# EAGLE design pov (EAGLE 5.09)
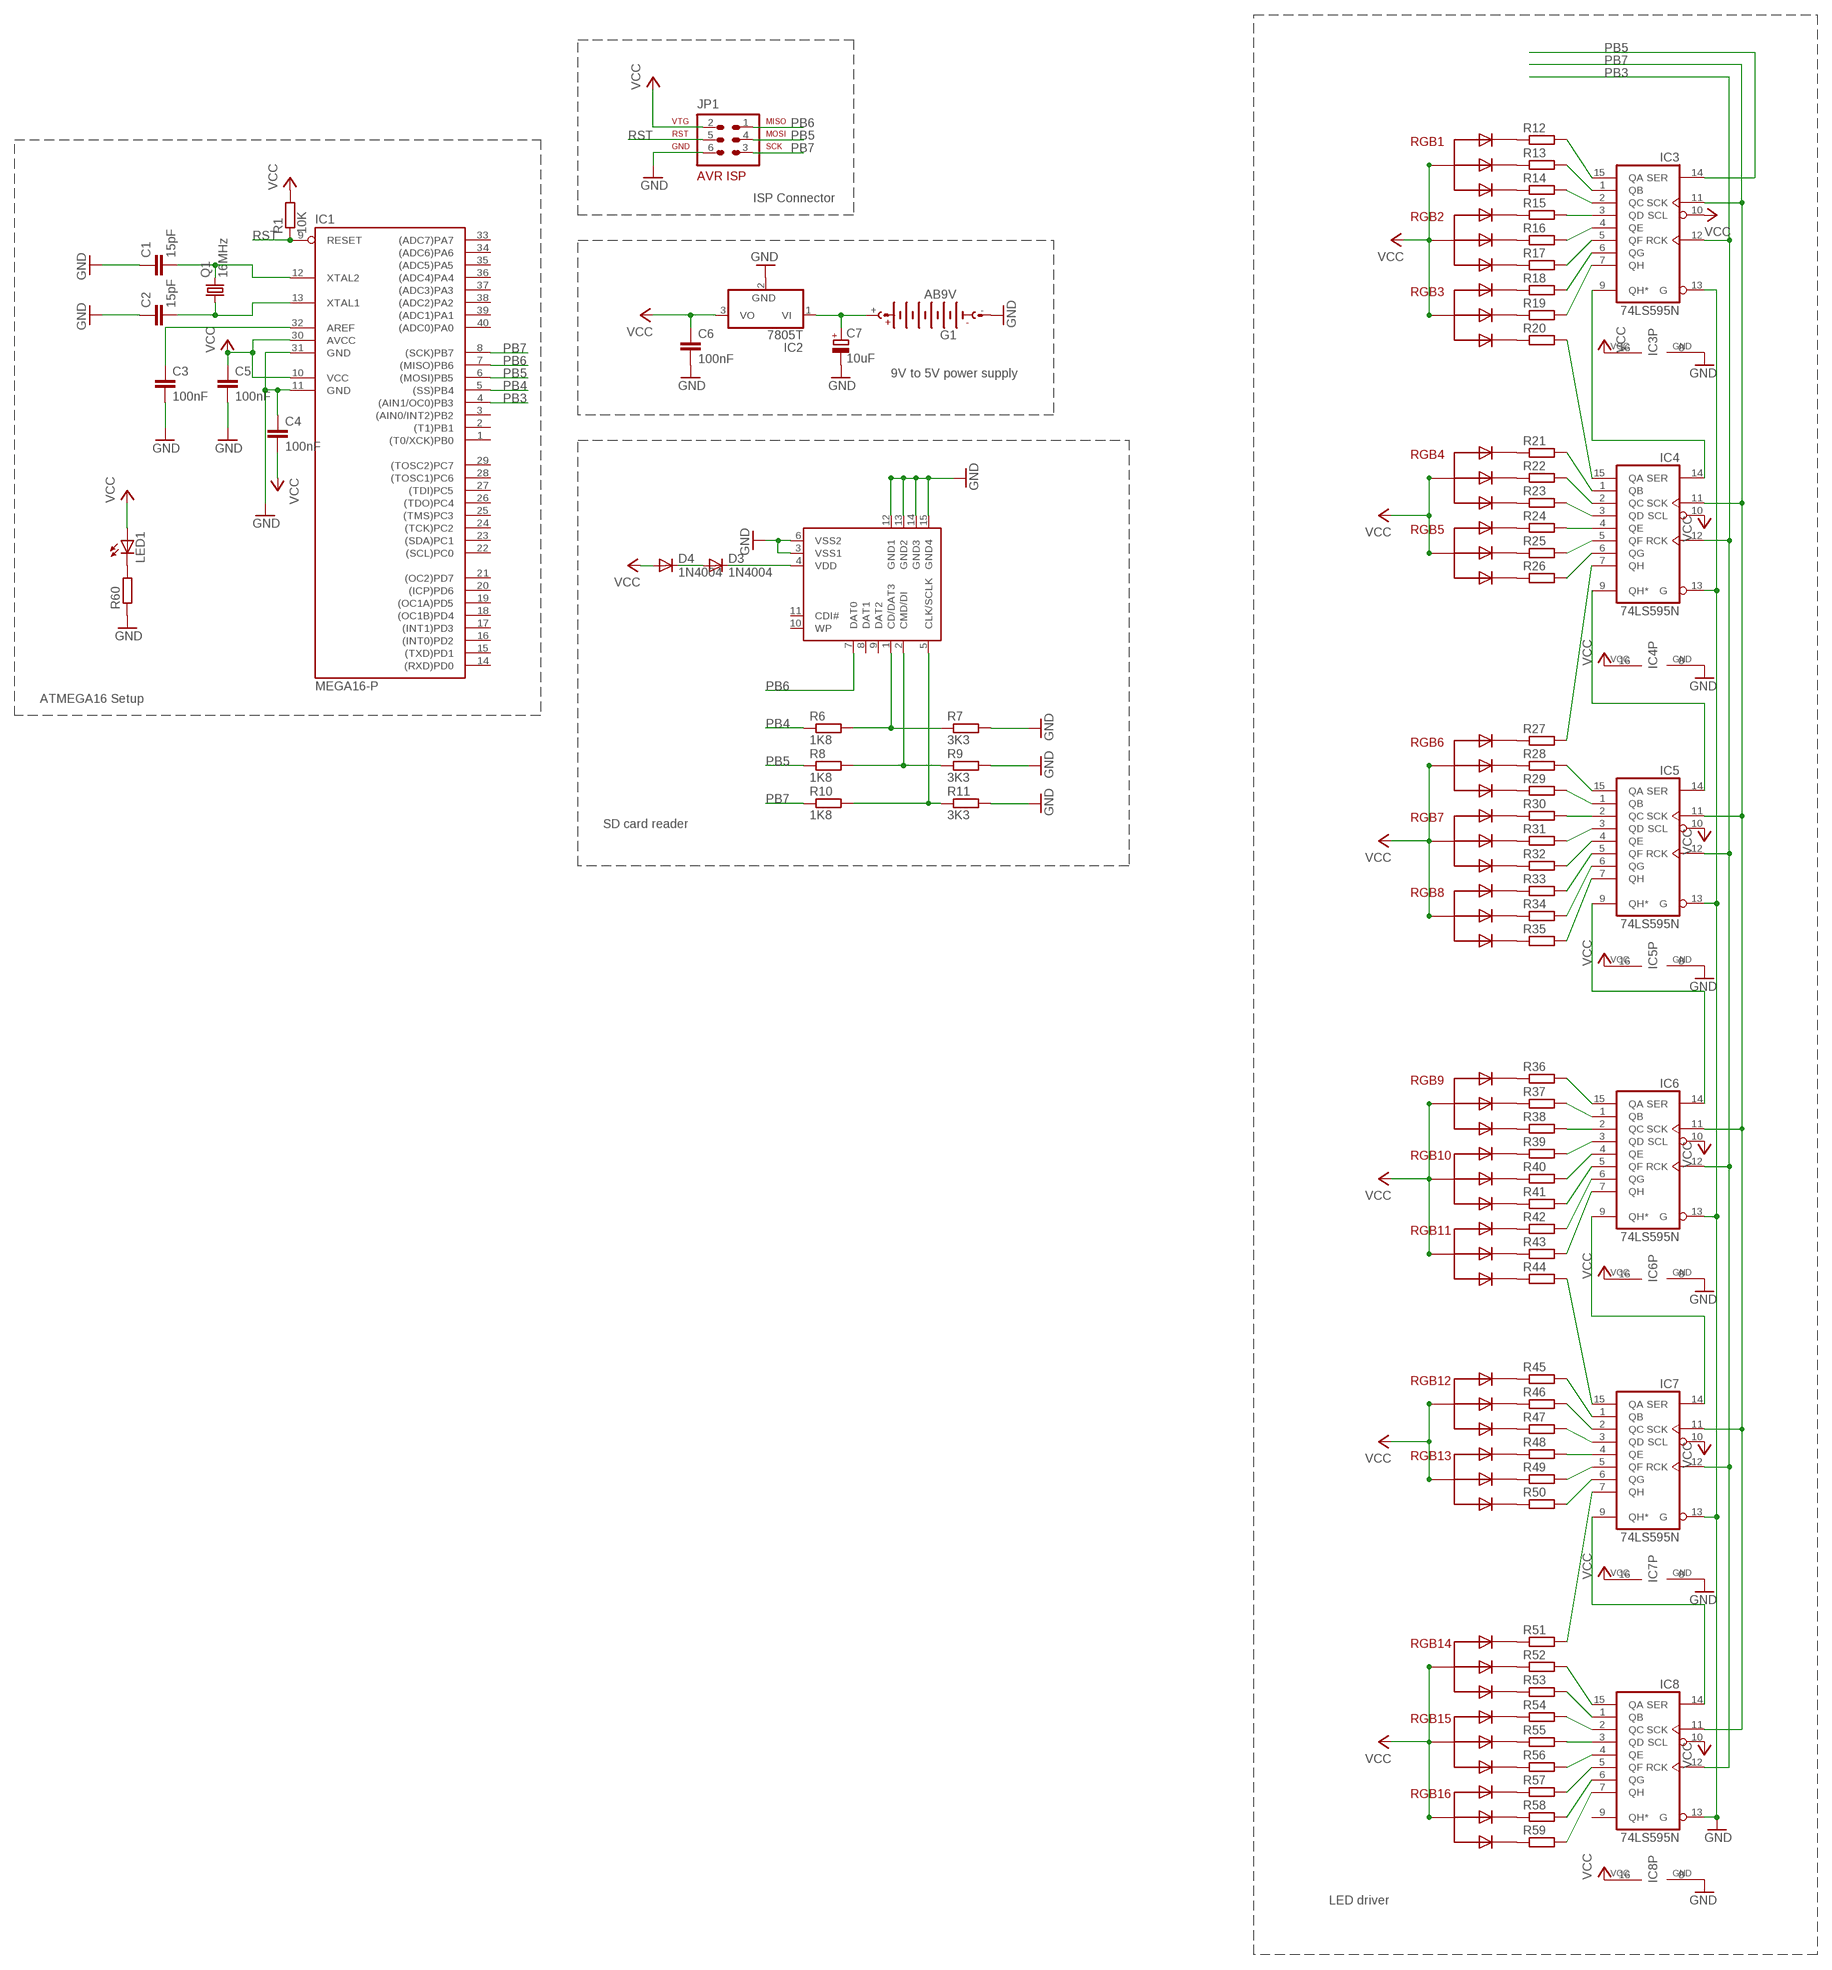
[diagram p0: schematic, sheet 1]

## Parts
C1  15pF  C-EU050-025X075  [C050-025X075]
C2  15pF  C-EU050-025X075  [C050-025X075]
C3  100nF  C-EU050-025X075  [C050-025X075]
C4  100nF  C-EU050-025X075  [C050-025X075]
C5  100nF  C-EU050-025X075  [C050-025X075]
C6  100nF  C-EU050-025X075  [C050-025X075]
C7  10uF  CPOL-EUE2,5-6E  [E2,5-6E]
D3  1N4004  [DO41-10]
D4  1N4004  [DO41-10]
G1  AB9V  [AB9V]
IC1  MEGA16-P  [DIL40]
IC2  7805T  [TO220H]
IC3  74LS595N  [DIL16]
IC4  74LS595N  [DIL16]
IC5  74LS595N  [DIL16]
IC6  74LS595N  [DIL16]
IC7  74LS595N  [DIL16]
IC8  74LS595N  [DIL16]
JP1  AVR-ISP-6  [AVR-ISP-6]
LED1  LED5MM  [LED5MM]
Q1  16MHz  CRYSTALHC49S  [HC49/S]
R1  10K  R-EU_0207/10  [0207/10]
R6  1K8  R-EU_0207/10  [0207/10]
R7  3K3  R-EU_0207/10  [0207/10]
R8  1K8  R-EU_0207/10  [0207/10]
R9  3K3  R-EU_0207/10  [0207/10]
R10  1K8  R-EU_0207/10  [0207/10]
R11  3K3  R-EU_0207/10  [0207/10]
R12  R-EU_M1206  [M1206]
R13  R-EU_M1206  [M1206]
R14  R-EU_M1206  [M1206]
R15  R-EU_M1206  [M1206]
R16  R-EU_M1206  [M1206]
R17  R-EU_M1206  [M1206]
R18  R-EU_M1206  [M1206]
R19  R-EU_M1206  [M1206]
R20  R-EU_M1206  [M1206]
R21  R-EU_M1206  [M1206]
R22  R-EU_M1206  [M1206]
R23  R-EU_M1206  [M1206]
R24  R-EU_M1206  [M1206]
R25  R-EU_M1206  [M1206]
R26  R-EU_M1206  [M1206]
R27  R-EU_M1206  [M1206]
R28  R-EU_M1206  [M1206]
R29  R-EU_M1206  [M1206]
R30  R-EU_M1206  [M1206]
R31  R-EU_M1206  [M1206]
R32  R-EU_M1206  [M1206]
R33  R-EU_M1206  [M1206]
R34  R-EU_M1206  [M1206]
R35  R-EU_M1206  [M1206]
R36  R-EU_M1206  [M1206]
R37  R-EU_M1206  [M1206]
R38  R-EU_M1206  [M1206]
R39  R-EU_M1206  [M1206]
R40  R-EU_M1206  [M1206]
R41  R-EU_M1206  [M1206]
R42  R-EU_M1206  [M1206]
R43  R-EU_M1206  [M1206]
R44  R-EU_M1206  [M1206]
R45  R-EU_M1206  [M1206]
R46  R-EU_M1206  [M1206]
R47  R-EU_M1206  [M1206]
R48  R-EU_M1206  [M1206]
R49  R-EU_M1206  [M1206]
R50  R-EU_M1206  [M1206]
R51  R-EU_M1206  [M1206]
R52  R-EU_M1206  [M1206]
R53  R-EU_M1206  [M1206]
R54  R-EU_M1206  [M1206]
R55  R-EU_M1206  [M1206]
R56  R-EU_M1206  [M1206]
R57  R-EU_M1206  [M1206]
R58  R-EU_M1206  [M1206]
R59  R-EU_M1206  [M1206]
R60  R-EU_0207/12  [0207/12]
RGB1  5MMRGBLEDAC  [LED5MMRGBAC]
RGB2  5MMRGBLEDAC  [LED5MMRGBAC]
RGB3  5MMRGBLEDAC  [LED5MMRGBAC]
RGB4  5MMRGBLEDAC  [LED5MMRGBAC]
RGB5  5MMRGBLEDAC  [LED5MMRGBAC]
RGB6  5MMRGBLEDAC  [LED5MMRGBAC]
RGB7  5MMRGBLEDAC  [LED5MMRGBAC]
RGB8  5MMRGBLEDAC  [LED5MMRGBAC]
RGB9  5MMRGBLEDAC  [LED5MMRGBAC]
RGB10  5MMRGBLEDAC  [LED5MMRGBAC]
RGB11  5MMRGBLEDAC  [LED5MMRGBAC]
RGB12  5MMRGBLEDAC  [LED5MMRGBAC]
RGB13  5MMRGBLEDAC  [LED5MMRGBAC]
RGB14  5MMRGBLEDAC  [LED5MMRGBAC]
RGB15  5MMRGBLEDAC  [LED5MMRGBAC]
RGB16  5MMRGBLEDAC  [LED5MMRGBAC]
U$1  SDCARDVAR2  [SDCMF-10915W010]

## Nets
GND: C1.1 C2.1 C3.2 C4.1 C5.2 C6.2 C7.- G1.- IC1.11(GND) IC1.31(GND) IC2.2(GND) IC3.8(GND) IC3.13(G) IC4.8(GND) IC4.13(G) IC5.8(GND) IC5.13(G) IC6.8(GND) IC6.13(G) IC7.8(GND) IC7.13(G) IC8.8(GND) IC8.13(G) JP1.6 R7.2 R9.2 R11.2 R60.1 U$1.3(VSS1) U$1.6(VSS2) U$1.12(GND1) U$1.13(GND2) U$1.14(GND3) U$1.15(GND4)
N$1: IC7.9(QH*) IC8.14(SER)
N$2: IC6.9(QH*) IC7.14(SER)
N$3: LED1.K(C) R60.2
N$4: R12.1 RGB1.RED
N$5: R13.1 RGB1.GRN(GREEN)
N$6: R14.1 RGB1.BLU(BLUE)
N$7: R15.1 RGB2.RED
N$8: R16.1 RGB2.GRN(GREEN)
N$9: R17.1 RGB2.BLU(BLUE)
N$10: R18.1 RGB3.RED
N$11: R19.1 RGB3.GRN(GREEN)
N$12: R20.1 RGB3.BLU(BLUE)
N$13: R21.1 RGB4.RED
N$14: R22.1 RGB4.GRN(GREEN)
N$15: R23.1 RGB4.BLU(BLUE)
N$16: R24.1 RGB5.RED
N$23: R25.1 RGB5.GRN(GREEN)
N$24: R6.2 R7.1 U$1.1(CD/DAT3)
N$25: R8.2 R9.1 U$1.2(CMD/DI)
N$26: D3.C U$1.4(VDD)
N$27: D3.A D4.C
N$28: R10.2 R11.1 U$1.5(CLK/SCLK)
N$29: R26.1 RGB5.BLU(BLUE)
N$30: R51.1 RGB14.RED
N$31: R27.1 RGB6.RED
N$32: R28.1 RGB6.GRN(GREEN)
N$33: R29.1 RGB6.BLU(BLUE)
N$34: R30.1 RGB7.RED
N$35: R31.1 RGB7.GRN(GREEN)
N$36: R32.1 RGB7.BLU(BLUE)
N$37: R33.1 RGB8.RED
N$38: R34.1 RGB8.GRN(GREEN)
N$39: R35.1 RGB8.BLU(BLUE)
N$40: IC3.15(QA) R12.2
N$41: IC3.1(QB) R13.2
N$42: IC3.2(QC) R14.2
N$43: IC3.3(QD) R15.2
N$44: IC3.4(QE) R16.2
N$45: IC3.5(QF) R17.2
N$46: IC3.6(QG) R18.2
N$47: IC3.7(QH) R19.2
N$48: IC4.15(QA) R20.2
N$49: IC4.1(QB) R21.2
N$50: IC4.2(QC) R22.2
N$51: IC4.3(QD) R23.2
N$52: IC4.4(QE) R24.2
N$53: IC4.5(QF) R25.2
N$54: IC4.6(QG) R26.2
N$55: IC4.7(QH) R27.2
N$56: IC5.15(QA) R28.2
N$57: IC5.1(QB) R29.2
N$58: IC5.2(QC) R30.2
N$59: IC5.3(QD) R31.2
N$60: IC5.4(QE) R32.2
N$61: IC5.5(QF) R33.2
N$62: IC5.6(QG) R34.2
N$63: IC5.7(QH) R35.2
N$64: IC6.15(QA) R36.2
N$65: IC6.1(QB) R37.2
N$66: IC6.2(QC) R38.2
N$67: R36.1 RGB9.RED
N$68: R37.1 RGB9.GRN(GREEN)
N$69: R38.1 RGB9.BLU(BLUE)
N$70: R39.1 RGB10.RED
N$71: R40.1 RGB10.GRN(GREEN)
N$72: R41.1 RGB10.BLU(BLUE)
N$73: IC3.9(QH*) IC4.14(SER)
N$74: R42.1 RGB11.RED
N$75: R43.1 RGB11.GRN(GREEN)
N$76: R44.1 RGB11.BLU(BLUE)
N$77: IC6.3(QD) R39.2
N$78: IC6.4(QE) R40.2
N$79: IC6.5(QF) R41.2
N$80: IC6.6(QG) R42.2
N$81: IC6.7(QH) R43.2
N$83: IC7.15(QA) R44.2
N$84: R45.1 RGB12.RED
N$85: R46.1 RGB12.GRN(GREEN)
N$86: R47.1 RGB12.BLU(BLUE)
N$87: R48.1 RGB13.RED
N$88: R49.1 RGB13.GRN(GREEN)
N$89: R50.1 RGB13.BLU(BLUE)
N$91: IC7.1(QB) R45.2
N$92: IC7.2(QC) R46.2
N$93: IC7.3(QD) R47.2
N$94: IC7.4(QE) R48.2
N$95: IC7.5(QF) R49.2
N$96: IC7.6(QG) R50.2
N$97: R52.1 RGB14.GRN(GREEN)
N$98: R53.1 RGB14.BLU(BLUE)
N$99: R54.1 RGB15.RED
N$100: R55.1 RGB15.GRN(GREEN)
N$101: R56.1 RGB15.BLU(BLUE)
N$102: R57.1 RGB16.RED
N$103: IC5.9(QH*) IC6.14(SER)
N$104: R58.1 RGB16.GRN(GREEN)
N$105: R59.1 RGB16.BLU(BLUE)
N$106: IC7.7(QH) R51.2
N$107: IC8.15(QA) R52.2
N$108: IC8.1(QB) R53.2
N$109: IC8.2(QC) R54.2
N$110: IC8.3(QD) R55.2
N$111: IC8.4(QE) R56.2
N$112: IC8.5(QF) R57.2
N$113: IC8.6(QG) R58.2
N$114: IC4.9(QH*) IC5.14(SER)
N$115: IC8.7(QH) R59.2
N$120: C1.2 IC1.12(XTAL2) Q1.2
N$121: C2.2 IC1.13(XTAL1) Q1.1
N$122: C3.1 IC1.32(AREF)
PB3: IC1.4((AIN1/OC0)PB3) IC3.12(RCK) IC4.12(RCK) IC5.12(RCK) IC6.12(RCK) IC7.12(RCK) IC8.12(RCK)
PB4: IC1.5((SS)PB4) R6.1
PB5: IC1.6((MOSI)PB5) IC3.14(SER) JP1.4 R8.1
PB6: IC1.7((MISO)PB6) JP1.1 U$1.7(DAT0)
PB7: IC1.8((SCK)PB7) IC3.11(SCK) IC4.11(SCK) IC5.11(SCK) IC6.11(SCK) IC7.11(SCK) IC8.11(SCK) JP1.3 R10.1
RST: IC1.9(RESET) JP1.5 R1.1
VCC: C4.2 C5.1 C6.1 D4.A IC1.10(VCC) IC1.30(AVCC) IC2.3(VO) IC3.10(SCL) IC3.16(VCC) IC4.10(SCL) IC4.16(VCC) IC5.10(SCL) IC5.16(VCC) IC6.10(SCL) IC6.16(VCC) IC7.10(SCL) IC7.16(VCC) IC8.10(SCL) IC8.16(VCC) JP1.2 LED1.A R1.2 RGB1.VCC RGB2.VCC RGB3.VCC RGB4.VCC RGB5.VCC RGB6.VCC RGB7.VCC RGB8.VCC RGB9.VCC RGB10.VCC RGB11.VCC RGB12.VCC RGB13.VCC RGB14.VCC RGB15.VCC RGB16.VCC
VCC9V: C7.+ G1.+ IC2.1(VI)
Unconnected: IC1.1((T0/XCK)PB0) IC1.2((T1)PB1) IC1.3((AIN0/INT2)PB2) IC1.14((RXD)PD0) IC1.15((TXD)PD1) IC1.16((INT0)PD2) IC1.17((INT1)PD3) IC1.18((OC1B)PD4) IC1.19((OC1A)PD5) IC1.20((ICP)PD6) IC1.21((OC2)PD7) IC1.22((SCL)PC0) IC1.23((SDA)PC1) IC1.24((TCK)PC2) IC1.25((TMS)PC3) IC1.26((TDO)PC4) IC1.27((TDI)PC5) IC1.28((TOSC1)PC6) IC1.29((TOSC2)PC7) IC1.33((ADC7)PA7) IC1.34((ADC6)PA6) IC1.35((ADC5)PA5) IC1.36((ADC4)PA4) IC1.37((ADC3)PA3) IC1.38((ADC2)PA2) IC1.39((ADC1)PA1) IC1.40((ADC0)PA0) IC8.9(QH*) U$1.8(DAT1) U$1.9(DAT2) U$1.10(WP) U$1.11(CDI#)

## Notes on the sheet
- ISP Connector
- 9V to 5V power supply
- ATMEGA16 Setup
- SD card reader
- LED driver

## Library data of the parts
C1-C6 = rcl:C-EU: CAPACITOR, European symbol
C7 = rcl:CPOL-EU: POLARIZED CAPACITOR, European symbol
D3 D4 = diode:1N4004: DIODE
G1 = battery:AB9V: 9-V BATTERY CLIP
IC1 = atmel:MEGA16-P: MICROCONTROLLER 16 Kbytes FLASH 1 kbytes SRAM 512 bytes EEPROM USART 8-channel 10 bit ADC Source: avr.lbr
IC2 = linear:78*: Positive VOLTAGE REGULATOR Source: http://cache.national.com/ds/LM/LM78L05.pdf http://www.fairchildsemi.com/ds/LM/LM7805.pdf
IC3-IC8 = 74xx-us:74*595: 8-bit SHIFT REGISTER, output latch
JP1 = avr-5:AVR-ISP-6: AVR ISP-6 Serial Programming Header
LED1 = led:LED: LED
Q1 = crystal:CRYSTAL: CRYSTAL
R1 R12-R60 = rcl:R-EU_: RESISTOR, European symbol
R6-R11 = resistor:R-EU_: RESISTOR, European symbol
RGB1-RGB16 = led_rgb2:5MMRGBLEDAC
U$1 = kingfont_sdcmf10915w010_covek:SDCARD: SD card connector KINGFONT SDCMF-10915W010

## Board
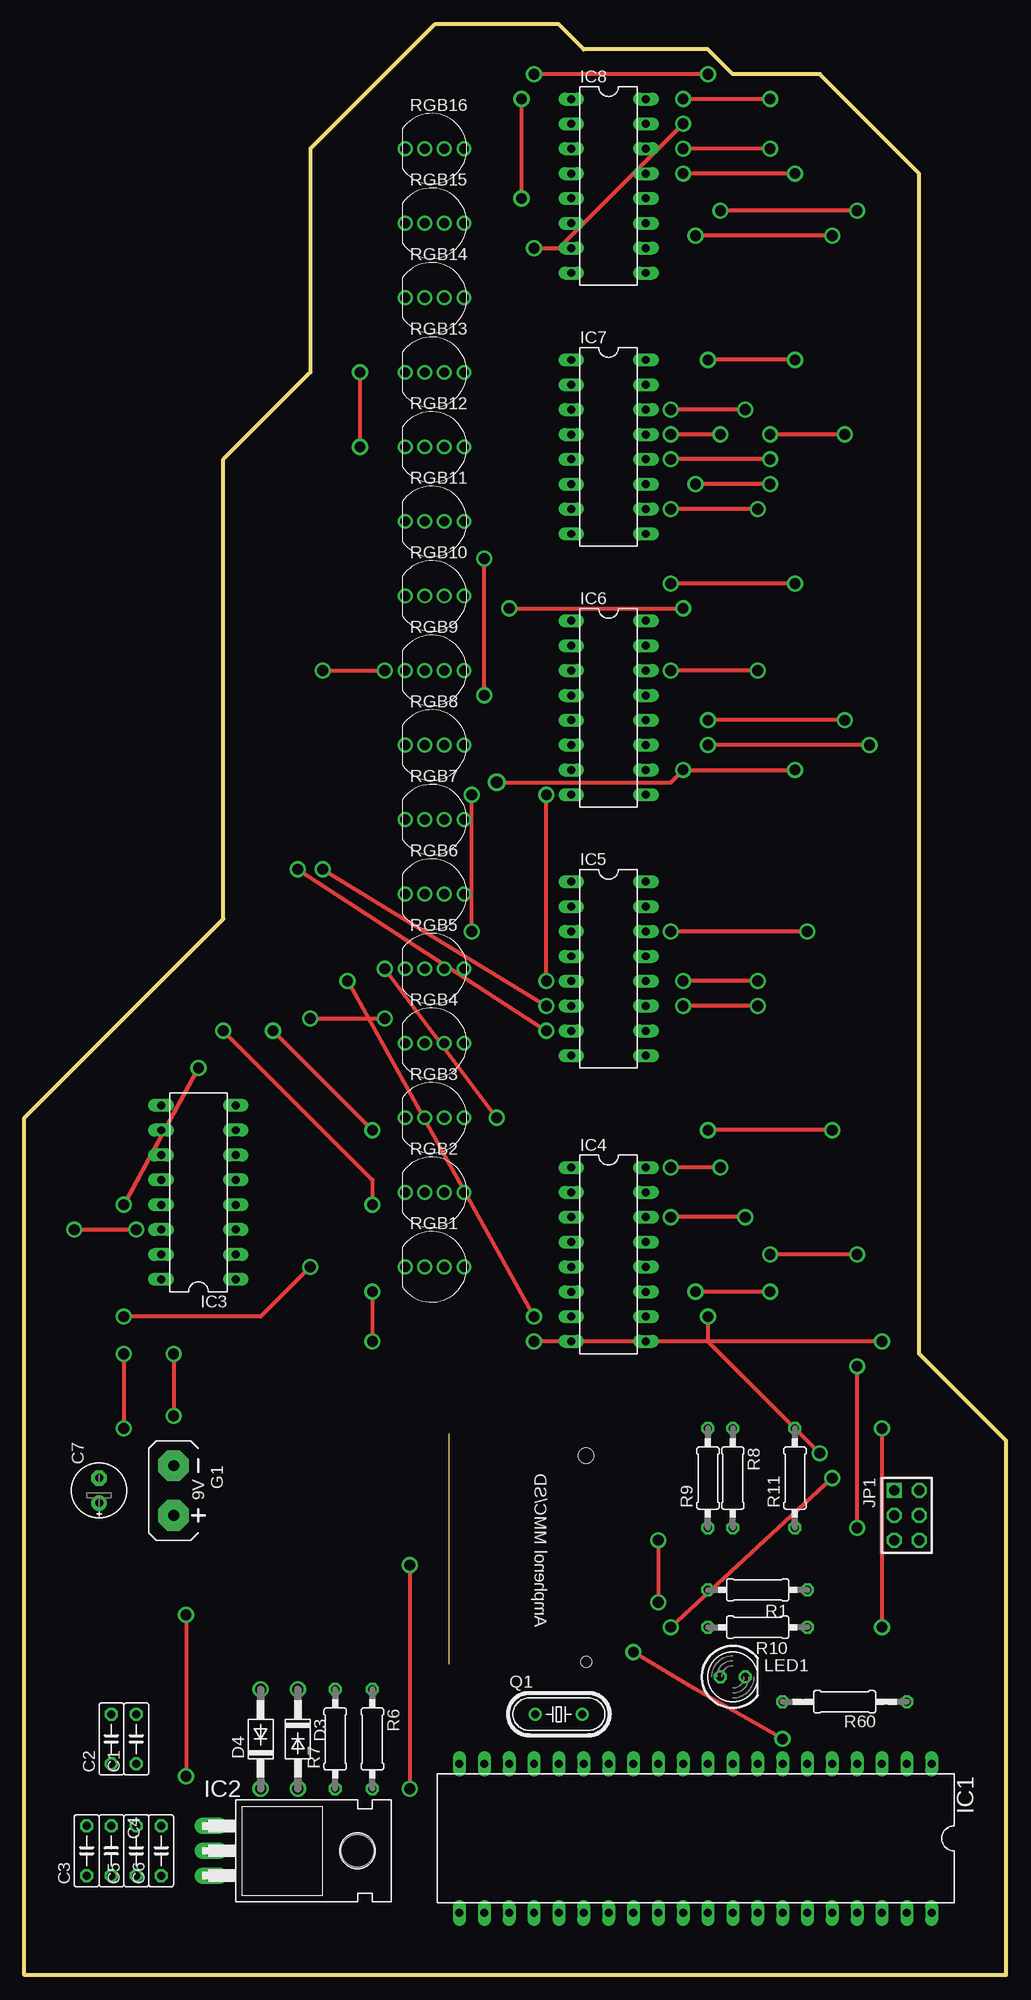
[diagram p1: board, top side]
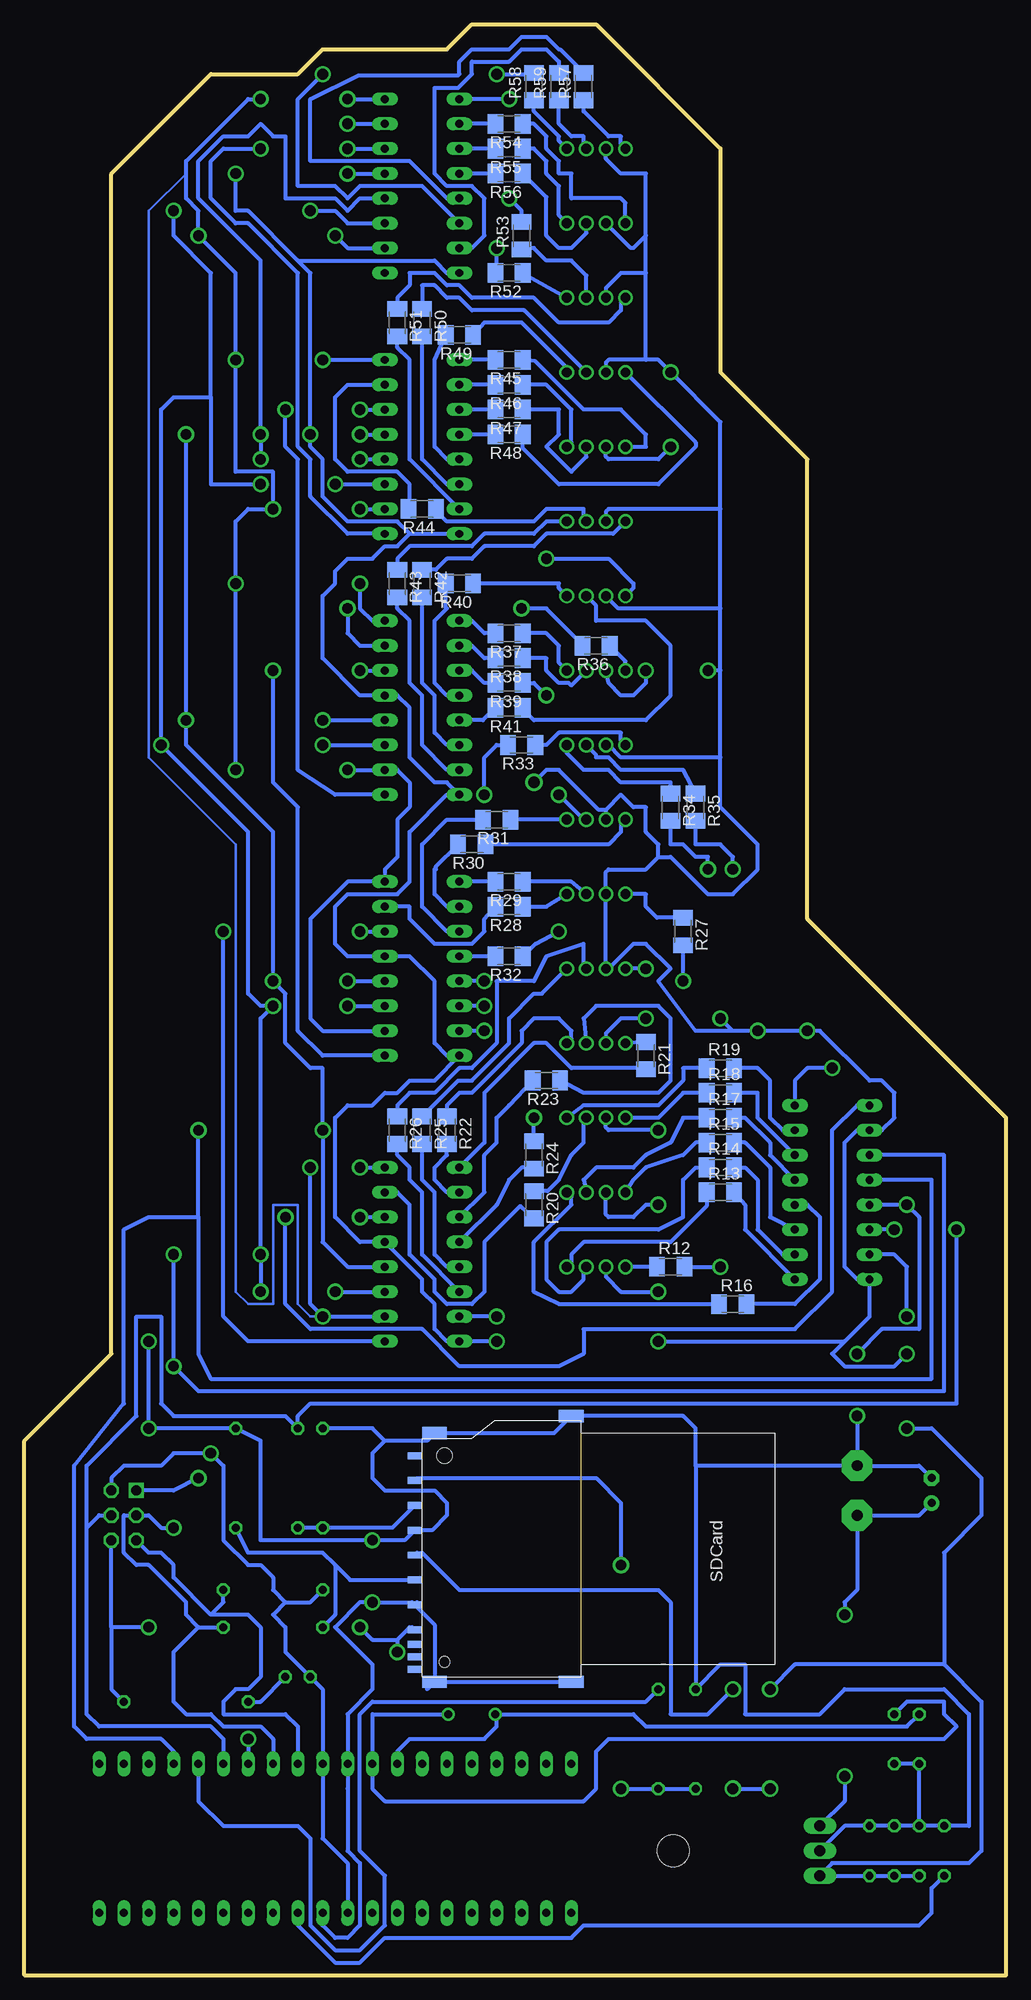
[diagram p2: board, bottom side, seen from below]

Size 100.33 x 199.39 mm. Coordinates in mm from the lower left corner, seen from the top.
Outline: 100.33,0 100.33,54.61 91.44,63.5 91.44,184.15 81.28,194.31 72.39,194.31 69.85,196.85 57.15,196.85 54.61,199.39 41.91,199.39 29.21,186.69 29.21,163.83 20.32,154.94 20.32,107.95 0,87.63 0,0 100.33,0
Copper layers (1*16): Top 0.035mm / dielectric 1.5mm / Bottom 0.035mm
Design rules "default": minimum track width 10mil, minimum drill 24mil, track to track 8mil, track to pad 8mil, pad to pad 8mil, via to via 8mil, smd to smd 8mil, copper to edge 40mil, drill to drill 8mil, minimum pad ring 10mil, minimum via ring 8mil, stop-mask expansion 4mil, vias tented up to drill 0mil, thermal gap 10mil

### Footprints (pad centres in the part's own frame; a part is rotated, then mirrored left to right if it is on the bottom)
C050-025X075 = drill 0.813 octagon: 1 -2.54,0; 2 2.54,0
E2,5-6E = drill 0.813 pad 1.575 round: + -1.27,0 | drill 0.813 pad 1.575 octagon: - 1.27,0
DO41-10 = drill 1.118 round: A 5.08,0; C -5.08,0
AB9V = drill 1.118 pad 3.15 octagon: + 0,2.54; - 0,-2.54
DIL40 = drill 0.813 long: 1 -24.13,-7.62; 2 -21.59,-7.62; 3 -19.05,-7.62; 4 -16.51,-7.62; 5 -13.97,-7.62; 6 -11.43,-7.62; 7 -8.89,-7.62; 8 -6.35,-7.62; 9 -3.81,-7.62; 10 -1.27,-7.62; 11 1.27,-7.62; 12 3.81,-7.62; 13 6.35,-7.62; 14 8.89,-7.62; 15 11.43,-7.62; 16 13.97,-7.62; 17 16.51,-7.62; 18 19.05,-7.62; 19 21.59,-7.62; 20 24.13,-7.62; 21 24.13,7.62; 22 21.59,7.62; 23 19.05,7.62; 24 16.51,7.62; 25 13.97,7.62; 26 11.43,7.62; 27 8.89,7.62; 28 6.35,7.62; 29 3.81,7.62; 30 1.27,7.62; 31 -1.27,7.62; 32 -3.81,7.62; 33 -6.35,7.62; 34 -8.89,7.62; 35 -11.43,7.62; 36 -13.97,7.62; 37 -16.51,7.62; 38 -19.05,7.62; 39 -21.59,7.62; 40 -24.13,7.62
TO220H = drill 1.118 long: 1 -2.54,-10.16; 2 0,-10.16; 3 2.54,-10.16 | hole 3.302: 0,4.826
DIL16 = drill 0.813 long: 1 -8.89,-3.81; 2 -6.35,-3.81; 3 -3.81,-3.81; 4 -1.27,-3.81; 5 1.27,-3.81; 6 3.81,-3.81; 7 6.35,-3.81; 8 8.89,-3.81; 9 8.89,3.81; 10 6.35,3.81; 11 3.81,3.81; 12 1.27,3.81; 13 -1.27,3.81; 14 -3.81,3.81; 15 -6.35,3.81; 16 -8.89,3.81
AVR-ISP-6 = drill 1.016 square: 1 -2.54,-1.27 | drill 1.016 octagon: 2 -2.54,1.27; 3 0,-1.27; 4 0,1.27; 5 2.54,-1.27; 6 2.54,1.27
LED5MM = drill 0.813 octagon: A -1.27,0; K 1.27,0
HC49/S = drill 0.813 round: 1 -2.413,0; 2 2.413,0
0207/10 = drill 0.813 octagon: 1 -5.08,0; 2 5.08,0
M1206 = smd 1.6 x 2: 1 -1.4,0; 2 1.4,0
0207/12 = drill 0.813 octagon: 1 -6.35,0; 2 6.35,0
LED5MMRGBAC = drill 1 round: BLU 1,0; GRN 3,0; RED -3,0; VCC -1,0
SDCMF-10915W010 = smd 0.711 x 1.422: 1 7.366,13.462; 2 4.826,13.462; 3 2.286,13.462; 4 -0.254,13.462; 5 -2.794,13.462; 6 -5.334,13.462; 7 -7.874,13.462; 8 -9.398,13.462; 9 9.906,13.462; 10 -11.938,13.462; 11 -10.668,13.462 | smd 1.27 x 2.54: 12 12.192,11.43; 13 13.97,-2.54; 14 -13.208,-2.54; 15 -13.208,11.43 | hole 1.6: 9.906,10.414 | hole 1.1: -11.176,10.414

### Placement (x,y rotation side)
C1  11.43,24.13 90 top
C2  8.89,24.13 90 top
C3  6.35,12.7 90 top
C4  8.89,12.7 270 top
C5  11.43,12.7 90 top
C6  13.97,12.7 90 top
C7  7.62,49.53 90 top
D3  27.94,24.13 270 top
D4  24.13,24.13 90 top
G1  15.24,49.53 180 top
IC1  68.58,13.97 180 top
IC2  29.21,12.7 270 top
IC3  17.78,80.01 90 top
IC4  59.69,73.66 270 top
IC5  59.69,102.87 270 top
IC6  59.69,129.54 270 top
IC7  59.69,156.21 270 top
IC8  59.69,182.88 270 top
JP1  90.17,46.99 270 top
LED1  72.39,30.48 0 top
Q1  54.61,26.67 0 top
R1  74.93,39.37 180 top
R6  35.56,24.13 270 top
R7  31.75,24.13 90 top
R8  72.39,50.8 270 top
R9  69.85,50.8 90 top
R10  74.93,35.56 180 top
R11  78.74,50.8 90 top
R12  34.29,72.39 0 bottom
R13  29.21,80.01 0 bottom
R14  29.21,82.55 0 bottom
R15  29.21,85.09 0 bottom
R16  27.94,68.58 0 bottom
R17  29.21,87.63 0 bottom
R18  29.21,90.17 0 bottom
R19  29.21,92.71 0 bottom
R20  48.26,78.74 270 bottom
R21  36.83,93.98 270 bottom
R22  57.15,86.36 270 bottom
R23  46.99,91.44 180 bottom
R24  48.26,83.82 270 bottom
R25  59.69,86.36 270 bottom
R26  62.23,86.36 270 bottom
R27  33.02,106.68 270 bottom
R28  50.8,109.22 180 bottom
R29  50.8,111.76 180 bottom
R30  54.61,115.57 180 bottom
R31  52.07,118.11 180 bottom
R32  50.8,104.14 180 bottom
R33  49.53,125.73 180 bottom
R34  34.29,119.38 270 bottom
R35  31.75,119.38 270 bottom
R36  41.91,135.89 180 bottom
R37  50.8,137.16 180 bottom
R38  50.8,134.62 180 bottom
R39  50.8,132.08 180 bottom
R40  55.88,142.24 180 bottom
R41  50.8,129.54 180 bottom
R42  59.69,142.24 270 bottom
R43  62.23,142.24 270 bottom
R44  59.69,149.86 180 bottom
R45  50.8,165.1 180 bottom
R46  50.8,162.56 180 bottom
R47  50.8,160.02 180 bottom
R48  50.8,157.48 180 bottom
R49  55.88,167.64 180 bottom
R50  59.69,168.91 270 bottom
R51  62.23,168.91 270 bottom
R52  50.8,173.99 180 bottom
R53  49.53,177.8 90 bottom
R54  50.8,189.23 180 bottom
R55  50.8,186.69 180 bottom
R56  50.8,184.15 180 bottom
R57  43.18,193.04 90 bottom
R58  48.26,193.04 90 bottom
R59  45.72,193.04 90 bottom
R60  83.82,27.94 180 top
RGB1  41.91,72.39 0 top
RGB2  41.91,80.01 0 top
RGB3  41.91,87.63 0 top
RGB4  41.91,95.25 0 top
RGB5  41.91,102.87 0 top
RGB6  41.91,110.49 0 top
RGB7  41.91,118.11 0 top
RGB8  41.91,125.73 0 top
RGB9  41.91,133.35 0 top
RGB10  41.91,140.97 0 top
RGB11  41.91,148.59 0 top
RGB12  41.91,156.21 0 top
RGB13  41.91,163.83 0 top
RGB14  41.91,171.45 0 top
RGB15  41.91,179.07 0 top
RGB16  41.91,186.69 0 top
U$1  46.99,43.18 90 bottom

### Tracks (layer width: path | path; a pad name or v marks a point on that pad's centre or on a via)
GND  (via drill 1.1)
  Top 0.406: v78.74,184.15 v67.31,184.15 | v71.12,157.48 v66.04,157.48 | v17.78,92.71 v10.16,78.74 | v15.24,63.5 v15.24,57.15 | v64.77,44.45 v64.77,38.1 | v87.63,55.88 v87.63,35.56 | v87.63,64.77 v52.07,64.77
  Bottom 0.406: v67.31,184.15 IC8.13 | IC8.8 57.15,173.99 58.42,175.26 72.39,175.26 | 60.96,147.32 IC7.8 | 60.96,147.32 62.23,148.59 67.31,148.59 69.85,151.13 69.85,154.94 71.12,156.21 v71.12,157.48 71.12,173.99 72.39,175.26 | 72.39,175.26 77.47,180.34 78.74,180.34 v78.74,184.15 | v66.04,157.48 IC7.13 | 60.96,147.32 62.23,146.05 63.5,146.05 64.77,144.78 67.31,144.78 68.58,143.51 68.58,142.24 69.85,140.97 69.85,134.62 66.04,130.81 IC6.13 62.23,130.81 60.96,129.54 60.96,124.46 58.42,121.92 57.15,121.92 IC6.8 57.15,120.65 60.96,116.84 60.96,111.76 62.23,110.49 67.31,110.49 68.58,109.22 68.58,105.41 67.31,104.14 IC5.13 60.96,104.14 58.42,101.6 58.42,95.25 57.15,93.98 IC5.8 58.42,91.44 60.96,91.44 62.23,90.17 63.5,90.17 64.77,88.9 67.31,88.9 68.58,87.63 68.58,77.47 66.04,74.93 IC4.13 59.69,71.12 59.69,69.85 58.42,68.58 58.42,66.04 57.15,64.77 IC4.8 v52.07,64.77 | IC3.8 21.59,91.44 20.32,92.71 v17.78,92.71 | IC3.13 v10.16,78.74 8.89,77.47 8.89,66.04 12.7,66.04 v15.24,63.5 | C4.1 C3.2 3.81,15.24 3.81,26.67 6.35,29.21 16.51,29.21 19.05,26.67 26.67,26.67 26.67,31.75 29.21,31.75 R7.2 31.75,52.07 | C4.1 C5.2 C6.2 16.51,15.24 IC2.2 | C4.1 C2.1 C1.1 | G1.- 8.89,52.07 C7.- | 31.75,52.07 31.75,55.88 33.02,57.15 U$1.13 46.23,55.37 U$1.12 59.18,54.61 63.5,54.61 | 63.5,54.61 64.77,53.34 64.77,50.8 63.5,49.53 58.42,49.53 57.15,48.26 57.15,46.99 58.67,45.47 U$1.3 61.47,44.45 v64.77,44.45 76.2,44.45 76.2,54.61 R11.2 v87.63,55.88 v87.63,64.77 | 59.18,29.21 U$1.15 58.42,30.48 | IC1.11 67.31,26.67 64.77,29.21 64.77,31.75 68.58,35.56 66.04,38.1 v64.77,38.1 60.71,38.1 U$1.6
  Bottom 0.406: IC1.11 67.31,19.05 | G1.- 31.75,52.07 | U$1.6 58.42,35.81 58.42,30.48 | 91.44,35.56 91.44,29.21 R60.1 | 91.44,35.56 JP1.6 | IC1.11 67.31,12.7 66.04,11.43 66.04,5.08 67.31,3.81 68.58,3.81 69.85,5.08 IC1.31 | v15.24,57.15 G1.- | U$1.6 60.2,38.1 | U$1.14 57.91,29.97 58.42,30.48 | v87.63,35.56 91.44,35.56 | R9.2 64.77,55.88 63.5,54.61
N$1  (via drill 1.1)
  Top 0.406: v76.2,186.69 v67.31,186.69
  Bottom 0.406: v67.31,186.69 IC8.14 | v76.2,186.69 80.01,186.69 81.28,185.42 81.28,181.61 78.74,179.07 77.47,179.07 72.39,173.99 72.39,156.21 71.12,154.94 71.12,151.13 67.31,147.32 IC7.9
N$2  (via drill 1.1)
  Top 0.406: v73.66,160.02 v66.04,160.02
  Bottom 0.406: v66.04,160.02 IC7.14 | v73.66,160.02 73.66,156.21 72.39,154.94 72.39,123.19 68.58,120.65 IC6.9
N$3
  Bottom 0.406: R60.2 76.2,27.94 LED1.K
N$4
  Bottom 0.406: R12.1 RGB1.RED
N$5
  Bottom 0.406: R13.1 30.61,78.61 34.29,74.93 43.18,74.93 44.45,73.66 44.45,72.85 RGB1.GRN
N$6
  Bottom 0.406: R14.1 31.75,82.55 33.02,81.28 33.02,77.47 35.56,76.2 45.72,76.2 46.99,74.93 46.99,71.12 45.72,69.85 44.45,69.85 43.18,71.12 43.18,72.12 RGB1.BLU
N$7
  Bottom 0.406: R15.1 31.75,85.09 33.02,83.82 36.83,82.55 38.1,81.28 RGB2.RED
N$8
  Bottom 0.406: R16.1 45.72,68.58 48.26,69.85 48.26,74.93 44.45,78.74 44.45,79.55 RGB2.GRN
N$9
  Bottom 0.406: R17.1 33.02,87.63 34.29,85.09 36.83,83.82 38.1,82.55 41.91,82.55 43.18,81.28 RGB2.BLU
N$10
  Bottom 0.406: R18.1 33.02,90.17 35.56,87.63 RGB3.RED
N$11
  Bottom 0.406: R19.1 33.02,92.71 33.02,91.44 35.56,88.9 43.18,88.9 RGB3.GRN
N$12
  Bottom 0.406: R20.1 46.86,80.14 45.72,81.28 44.45,83.82 43.18,85.09 43.18,87.36 RGB3.BLU
N$13
  Bottom 0.406: R21.1 RGB4.RED
N$14
  Bottom 0.406: R22.1 57.15,88.9 55.88,90.17 54.61,90.17 49.53,95.25 49.53,96.52 48.26,97.79 45.72,97.79 44.45,96.52 44.45,95.71 RGB4.GRN
N$15
  Bottom 0.406: R23.1 43.18,90.17 35.56,90.17 34.29,91.44 34.29,97.79 35.56,99.06 41.91,99.06 43.18,97.79 RGB4.BLU
N$16  (via drill 1.1)
  Top 0.406: v48.26,87.63 v36.83,102.87
  Bottom 0.406: R24.1 v48.26,87.63 | v36.83,102.87 RGB5.RED
N$17  (via drill 1.1)
  other vias: 67.31,189.23
N$18  (via drill 1.1)
  other vias: 52.07,176.53
N$19  (via drill 1.1)
  other vias: 67.31,191.77
N$20  (via drill 1.1)
  other vias: 76.2,191.77
N$21  (via drill 1.1)
  other vias: 52.07,194.31
N$22  (via drill 1.1)
  other vias: 50.8,181.61
N$23
  Bottom 0.406: RGB5.GRN 47.45,100.33 48.26,100.33 50.8,97.79 50.8,95.25 54.61,91.44 56.01,91.44 R25.1
N$24  (via drill 1.1)
  Top 0.406: v39.37,41.91 v39.37,19.05
  Bottom 0.406: R7.1 R6.2 v39.37,19.05 | v39.37,41.91 39.37,48.26 41.91,50.8 60.2,50.8 U$1.1
N$25
  Bottom 0.406: U$1.2 62.74,45.72 R9.1 R8.2
N$26
  Bottom 0.406: D3.C 30.48,26.67 34.29,26.67 34.29,38.1 35.56,39.37 55.88,39.37 59.69,43.18 60.2,43.18 U$1.4
N$27
  Bottom 0.406: D3.A D4.C
N$28
  Bottom 0.406: R10.2 68.58,36.83 68.58,41.91 | R11.1 77.47,43.18 69.85,43.18 68.58,41.91 | U$1.5 67.06,40.39 68.58,41.91
N$29
  Bottom 0.406: RGB5.BLU 43.18,102.87 43.18,105.41 46.99,104.14 48.26,101.6 52.07,101.6 52.07,95.25 54.61,92.71 55.88,92.71 58.42,90.17 60.96,90.17 62.23,88.9 R26.1
N$30
  Bottom 0.406: R51.1 62.23,171.45 60.96,172.72 60.96,173.99 58.42,173.99 57.15,172.72 55.88,172.72 54.61,171.45 48.26,171.45 45.72,168.91 40.64,168.91 39.37,170.18 39.37,170.99 RGB14.RED
N$31
  Bottom 0.406: R27.1 35.69,108.08 36.83,109.22 36.83,110.49 RGB6.RED
N$32
  Bottom 0.406: R28.1 46.99,109.22 RGB6.GRN
N$33
  Bottom 0.406: R29.1 44.45,111.76 RGB6.BLU
N$34
  Bottom 0.406: R30.1 40.64,115.57 39.37,116.84 39.37,117.65 RGB7.RED
N$35
  Bottom 0.406: RGB7.GRN R31.1
N$36  (via drill 1.1)
  Top 0.406: v45.72,106.68 v45.72,120.65
  Bottom 0.406: RGB7.BLU 43.18,118.11 v45.72,120.65 | v45.72,106.68 48.13,105.41 R32.1
N$37
  Bottom 0.406: R33.1 46.99,125.73 45.72,127 39.37,127 39.37,126.19 RGB8.RED
N$38
  Bottom 0.406: RGB8.GRN 44.91,124.92 43.18,123.19 40.64,123.19 39.37,121.92 34.29,121.92 R34.1
N$39
  Bottom 0.406: R35.1 33.02,123.19 39.37,123.19 40.64,124.46 41.91,124.46 41.91,124.73 RGB8.BLU
N$40  (via drill 1.1)
  Top 0.406: v10.16,67.31 24.13,67.31 v29.21,72.39
  Bottom 0.406: R12.2 v29.21,72.39 | v10.16,67.31 10.16,72.39 11.43,73.66 IC3.15
N$41
  Bottom 0.406: R13.2 26.67,78.74 26.67,76.2 IC3.1
N$42
  Bottom 0.406: R14.2 26.67,82.55 25.4,81.28 25.4,76.2 22.86,73.66 IC3.2
N$43
  Bottom 0.406: R15.2 26.67,85.09 24.13,82.55 24.13,77.47 IC3.3
N$44
  Bottom 0.406: IC3.4 20.32,78.74 19.05,77.47 19.05,71.12 21.59,68.58 R16.2
N$45
  Bottom 0.406: R17.2 26.67,87.63 24.13,85.09 24.13,83.82 IC3.5
N$46
  Bottom 0.406: R18.2 25.4,90.17 25.4,87.63 IC3.6
N$47
  Bottom 0.406: R19.2 25.4,92.71 24.13,91.44 24.13,87.63 22.86,86.36 IC3.7
N$48
  Bottom 0.406: R20.2 49.66,78.61 53.34,74.93 53.34,69.85 54.61,68.58 57.15,68.58 58.42,69.85 58.42,71.12 60.96,73.66 60.96,78.74 62.23,80.01 IC4.15
N$49
  Bottom 0.406: IC4.1 53.34,85.09 53.34,90.17 48.26,95.25 46.99,95.25 44.45,92.71 36.96,92.71 R21.2
N$50
  Bottom 0.406: R22.2 57.15,83.82 58.42,82.55 58.42,81.28 57.15,80.01 IC4.2
N$51
  Bottom 0.406: IC4.3 53.34,80.01 53.34,83.82 52.07,85.09 52.07,87.63 50.8,88.9 R23.2
N$52
  Bottom 0.406: IC4.4 52.07,78.74 50.8,81.28 49.53,82.55 48.39,82.55 R24.2
N$53
  Bottom 0.406: R25.2 59.69,81.28 58.42,80.01 58.42,73.66 57.15,72.39 IC4.5
N$54
  Bottom 0.406: R26.2 62.23,83.82 60.96,82.55 60.96,81.28 59.69,80.01 59.69,73.66 IC4.6
N$55  (via drill 1.1)
  Top 0.406: v52.07,67.31 v33.02,101.6
  Bottom 0.406: v52.07,67.31 IC4.7 | v33.02,101.6 R27.2
N$56
  Bottom 0.406: R28.2 53.34,107.95 53.34,106.68 54.61,105.41 58.42,105.41 60.96,107.95 60.96,109.22 IC5.15
N$57
  Bottom 0.406: R29.2 IC5.1
N$58
  Bottom 0.406: IC5.2 57.15,109.22 58.42,110.49 58.42,113.03 58.29,113.03 58.29,113.29 R30.2
N$59
  Bottom 0.406: R31.2 57.15,118.11 59.69,115.57 59.69,109.22 57.15,106.68 IC5.3
N$60
  Bottom 0.406: R32.2 IC5.4
N$61  (via drill 1.1)
  Top 0.406: v53.34,101.6 v53.34,120.65
  Bottom 0.406: R33.2 52.07,125.73 53.34,124.46 v53.34,120.65 | v53.34,101.6 IC5.5
N$62  (via drill 1.1)
  Top 0.406: v30.48,113.03 v53.34,99.06
  Bottom 0.406: R34.2 34.29,115.57 33.02,115.57 31.75,114.3 30.48,114.3 v30.48,113.03 | v53.34,99.06 IC5.6
N$63  (via drill 1.1)
  Top 0.406: v27.94,113.03 v53.34,96.52
  Bottom 0.406: R35.2 31.75,115.57 29.21,115.57 27.94,114.3 v27.94,113.03 | v53.34,96.52 IC5.7
N$64  (via drill 1.1)
  Top 0.406: v49.53,139.7 v67.31,139.7
  Bottom 0.406: R36.2 43.31,136.02 46.99,139.7 v49.53,139.7 | v67.31,139.7 67.31,137.16 66.04,135.89 IC6.15
N$65
  Bottom 0.406: IC6.1 54.61,138.43 53.34,137.16 R37.2
N$66
  Bottom 0.406: IC6.2 54.61,135.89 53.34,134.62 R38.2
N$67
  Bottom 0.406: RGB9.RED 38.91,134.29 R36.1
N$68
  Bottom 0.406: R37.1 46.99,137.16 45.72,135.89 45.72,134.16 RGB9.GRN
N$69
  Bottom 0.406: R38.1 46.99,134.62 46.99,133.35 45.72,132.08 44.72,132.08 44.45,131.81 RGB9.BLU
N$70  (via drill 1.1)
  Top 0.406: v46.99,130.81 v46.99,144.78
  Bottom 0.406: R39.1 48.26,132.08 v46.99,130.81 | v46.99,144.78 40.64,144.78 38.1,142.24 38.1,141.78 RGB10.RED
N$71
  Bottom 0.406: R40.1 45.72,142.24 45.72,141.78 RGB10.GRN
N$72
  Bottom 0.406: RGB10.BLU 41.91,139.97 41.91,138.43 36.83,138.43 34.29,135.89 34.29,130.81 36.83,128.27 48.26,128.27 49.4,129.41 R41.1
N$73  (via drill 1.1)
  Top 0.406: v73.66,77.47 v66.04,77.47
  Bottom 0.406: v66.04,77.47 IC4.14 | v73.66,77.47 73.66,68.58 71.12,66.04 59.69,66.04 55.88,62.23 45.72,62.23 43.18,63.5 43.18,66.04 21.59,66.04 17.78,69.85 17.78,86.36 15.24,88.9 IC3.9
N$74
  Bottom 0.406: R42.1 58.29,143.64 57.15,144.78 54.61,144.78 53.34,146.05 48.26,146.05 46.99,147.32 40.18,147.32 RGB11.RED
N$75
  Bottom 0.406: R43.1 62.23,144.78 60.96,146.05 54.61,146.05 53.34,147.32 48.26,147.32 46.99,148.59 RGB11.GRN
N$76
  Bottom 0.406: R44.1 58.29,149.73 57.15,148.59 48.26,148.59 46.99,149.86 43.18,149.86 43.18,148.86 RGB11.BLU
N$77
  Bottom 0.406: IC6.3 54.61,133.35 53.34,132.08 R39.2
N$78
  Bottom 0.406: R40.2 57.28,139.83 57.15,139.7 58.42,138.43 58.42,132.08 57.15,130.81 IC6.4
N$79
  Bottom 0.406: IC6.5 53.47,128.27 R41.2
N$80
  Bottom 0.406: R42.2 59.69,132.08 58.42,130.81 58.42,127 57.15,125.73 IC6.6
N$81
  Bottom 0.406: R43.2 62.23,139.7 60.96,138.43 60.96,132.08 59.69,130.81 59.69,125.73 57.15,123.19 IC6.7
N$82  (via drill 1.1)
  other vias: 50.8,191.77
N$83
  Bottom 0.406: IC7.15 67.31,162.56 68.58,161.29 68.58,154.94 67.31,153.67 62.23,153.67 60.96,152.4 60.96,149.99 R44.2
N$84
  Bottom 0.406: R45.1 48.13,164.97 43.18,160.02 39.37,160.02 36.83,157.48 36.83,156.21 RGB12.RED
N$85
  Bottom 0.406: R46.1 46.99,162.56 44.45,160.02 44.45,156.67 RGB12.GRN
N$86
  Bottom 0.406: RGB12.BLU 42.91,155.21 44.45,153.67 46.99,156.21 45.72,157.48 45.72,160.02 R47.1
N$87
  Bottom 0.406: R48.1 49.4,156.08 45.72,152.4 35.56,152.4 31.75,156.21 31.75,156.67 RGB13.RED
N$88
  Bottom 0.406: RGB13.GRN 44.91,164.29 49.53,168.91 53.34,168.91 R49.1
N$89
  Bottom 0.406: R50.1 59.69,172.72 58.42,172.72 57.15,171.45 55.88,171.45 54.61,170.18 49.26,170.18 RGB13.BLU
N$90  (via drill 1.1)
  other vias: 67.31,184.15
N$91
  Bottom 0.406: R45.2 IC7.1
N$92
  Bottom 0.406: R46.2 IC7.2
N$93
  Bottom 0.406: R47.2 IC7.3
N$94
  Bottom 0.406: R48.2 IC7.4
N$95
  Bottom 0.406: IC7.5 57.15,154.94 58.42,156.21 58.42,165.1 R49.2
N$96
  Bottom 0.406: R50.2 59.69,154.94 57.15,152.4 IC7.6
N$97
  Bottom 0.406: RGB14.GRN R52.1
N$98
  Bottom 0.406: RGB14.BLU 42.91,173.72 44.45,175.26 46.99,175.26 48.26,176.53 49.4,176.53 R53.1
N$99
  Bottom 0.406: RGB15.RED 38.91,181.15 39.37,181.61 44.45,181.61 44.45,184.15 45.72,184.15 45.72,185.42 46.99,186.69 46.99,187.96 48.26,189.23 R54.1
N$100
  Bottom 0.406: R55.1 48.26,186.69 46.99,185.42 46.99,184.15 45.72,182.88 45.72,179.88 RGB15.GRN
N$101
  Bottom 0.406: RGB15.BLU 42.91,178.07 44.45,176.53 45.72,176.53 46.99,177.8 46.99,181.74 R56.1
N$102
  Bottom 0.406: R57.1 43.18,190.5 40.64,187.96 39.37,187.96 39.37,187.15 RGB16.RED
N$103  (via drill 1.1)
  Top 0.406: v74.93,133.35 v66.04,133.35
  Bottom 0.406: v66.04,133.35 IC6.14 | v74.93,133.35 74.93,121.92 72.39,119.38 72.39,96.52 69.85,93.98 IC5.9
N$104
  Bottom 0.406: R58.1 48.26,190.5 45.72,187.96 45.72,187.5 RGB16.GRN
N$105
  Bottom 0.406: R59.1 45.72,189.23 44.45,187.96 43.18,187.96 43.18,186.96 RGB16.BLU
N$106
  Bottom 0.406: R51.2 62.23,166.37 60.96,165.1 60.96,154.94 IC7.7
N$107  (via drill 1.1)
  Top 0.406: v52.07,176.53 54.61,176.53 v67.31,189.23
  Bottom 0.406: v67.31,189.23 IC8.15 | R52.2 52.07,173.99 v52.07,176.53
N$108  (via drill 1.1)
  Top 0.406: v50.8,181.61 v50.8,191.77
  Bottom 0.406: v50.8,191.77 IC8.1 | R53.2 49.53,180.34 v50.8,181.61
N$109
  Bottom 0.406: R54.2 IC8.2
N$110
  Bottom 0.406: R55.2 IC8.3
N$111
  Bottom 0.406: R56.2 IC8.4
N$112
  Bottom 0.406: IC8.5 57.15,181.61 60.96,185.42 71.12,185.42 71.12,191.77 66.17,194.18 56.01,194.18 55.88,194.31 55.88,195.58 54.61,196.85 50.8,196.85 49.53,198.12 46.99,198.12 45.72,196.85 45.59,196.85 R57.2
N$113  (via drill 1.1)
  Top 0.406: v69.85,194.31 v52.07,194.31
  Bottom 0.406: v69.85,194.31 72.39,191.77 72.39,182.88 68.58,182.88 67.31,181.61 66.04,182.88 59.69,182.88 IC8.6 | 48.26,194.31 R58.2 48.39,194.31 v52.07,194.31
N$114  (via drill 1.1)
  Top 0.406: v80.01,106.68 v66.04,106.68
  Bottom 0.406: v66.04,106.68 IC5.14 | v80.01,106.68 80.01,67.31 77.47,64.77 IC4.9
N$115
  Bottom 0.406: IC8.7 54.61,176.53 53.34,177.8 53.34,181.61 54.61,182.88 57.15,182.88 58.42,184.15 58.42,192.91 56.01,192.91 54.61,194.31 54.61,195.58 50.8,195.58 49.53,196.85 46.99,196.85 45.72,195.58 R59.2
N$116  (via drill 1.1)
  other vias: 78.74,184.15
N$117  (via drill 1.1)
  other vias: 34.29,156.21
N$118  (via drill 1.1)
  other vias: 34.29,163.83
N$119  (via drill 1.1)
  other vias: 66.04,157.48
N$120
  Bottom 0.406: Q1.2 64.77,26.67 IC1.12 64.77,19.05 63.5,17.78 43.18,17.78 41.91,19.05 41.91,22.86 40.64,24.13 6.35,24.13 5.08,25.4 6.35,26.67 6.35,27.94 10.16,27.94 C1.2
N$121
  Bottom 0.406: IC1.13 62.23,22.86 60.96,24.13 53.34,24.13 52.07,25.4 52.07,26.54 Q1.1 38.1,26.67 36.83,25.4 10.16,25.4 C2.2
N$122
  Bottom 0.406: C3.1 7.62,8.89 7.62,6.35 8.89,5.08 43.18,5.08 44.45,3.81 63.5,3.81 66.04,1.27 68.58,1.27 72.39,5.08 IC1.32
N$123  (via drill 1.1)
  other vias: 71.12,157.48
N$124  (via drill 1.1)
  other vias: 46.99,130.81
N$125  (via drill 1.1)
  other vias: 46.99,144.78
N$126  (via drill 1.1)
  other vias: 49.53,139.7
N$127  (via drill 1.1)
  other vias: 67.31,139.7
N$128  (via drill 1.1)
  other vias: 67.31,186.69
N$129  (via drill 1.1)
  other vias: 76.2,186.69
N$130  (via drill 1.1)
  other vias: 66.04,154.94
N$131  (via drill 1.1)
  other vias: 76.2,154.94
N$132  (via drill 1.1)
  other vias: 68.58,177.8
N$133  (via drill 1.1)
  other vias: 71.12,180.34
N$134  (via drill 1.1)
  other vias: 85.09,180.34
N$135  (via drill 1.1)
  other vias: 82.55,177.8
N$136  (via drill 1.1)
  other vias: 68.58,152.4
N$137  (via drill 1.1)
  other vias: 66.04,149.86
N$138  (via drill 1.1)
  other vias: 74.93,149.86
N$139  (via drill 1.1)
  other vias: 69.85,165.1
N$140  (via drill 1.1)
  other vias: 15.24,57.15
N$141  (via drill 1.1)
  other vias: 15.24,63.5
N$142  (via drill 1.1)
  other vias: 45.72,106.68
N$143  (via drill 1.1)
  other vias: 45.72,120.65
N$144  (via drill 1.1)
  other vias: 53.34,101.6
N$145  (via drill 1.1)
  other vias: 53.34,120.65
N$146  (via drill 1.1)
  other vias: 53.34,99.06
N$147  (via drill 1.1)
  other vias: 53.34,96.52
N$148  (via drill 1.1)
  other vias: 36.83,133.35
N$149  (via drill 1.1)
  other vias: 30.48,133.35
N$150  (via drill 1.1)
  other vias: 30.48,113.03
N$151  (via drill 1.1)
  other vias: 27.94,113.03
N$152  (via drill 1.1)
  other vias: 48.26,87.63
N$153  (via drill 1.1)
  other vias: 36.83,102.87
N$154  (via drill 1.1)
  other vias: 33.02,101.6
N$155  (via drill 1.1)
  other vias: 52.07,67.31
N$156  (via drill 1.1)
  other vias: 29.21,72.39
N$157  (via drill 1.1)
  other vias: 10.16,67.31
N$158  (via drill 1.1)
  other vias: 36.83,97.79
N$159  (via drill 1.1)
  other vias: 29.21,97.79
N$160  (via drill 1.1)
  other vias: 35.56,86.36
N$161  (via drill 1.1)
  other vias: 25.4,96.52
N$162  (via drill 1.1)
  other vias: 35.56,78.74
N$163  (via drill 1.1)
  other vias: 20.32,96.52
N$164  (via drill 1.1)
  other vias: 35.56,69.85
N$165  (via drill 1.1)
  other vias: 35.56,64.77
N$166  (via drill 1.1)
  other vias: 66.04,160.02
N$167  (via drill 1.1)
  other vias: 73.66,160.02
N$168  (via drill 1.1)
  other vias: 66.04,142.24
N$169  (via drill 1.1)
  other vias: 78.74,142.24
N$170  (via drill 1.1)
  other vias: 67.31,123.19
N$171  (via drill 1.1)
  other vias: 78.74,123.19
N$172  (via drill 1.1)
  other vias: 83.82,157.48
N$173  (via drill 1.1)
  other vias: 83.82,128.27
N$174  (via drill 1.1)
  other vias: 69.85,128.27
N$176  (via drill 1.1)
  other vias: 86.36,125.73
N$177  (via drill 1.1)
  other vias: 69.85,125.73
N$178  (via drill 1.1)
  other vias: 66.04,133.35
N$179  (via drill 1.1)
  other vias: 74.93,133.35
N$180  (via drill 1.1)
  other vias: 67.31,101.6
N$181  (via drill 1.1)
  other vias: 74.93,101.6
N$182  (via drill 1.1)
  other vias: 67.31,99.06
N$183  (via drill 1.1)
  other vias: 74.93,99.06
N$184  (via drill 1.1)
  other vias: 66.04,77.47
N$185  (via drill 1.1)
  other vias: 66.04,82.55
N$186  (via drill 1.1)
  other vias: 66.04,106.68
N$187  (via drill 1.1)
  other vias: 73.66,77.47
N$188  (via drill 1.1)
  other vias: 71.12,82.55
N$189  (via drill 1.1)
  other vias: 80.01,106.68
N$190  (via drill 1.1)
  other vias: 17.78,92.71
N$191  (via drill 1.1)
  other vias: 85.09,73.66
N$192  (via drill 1.1)
  other vias: 68.58,69.85
N$193  (via drill 1.1)
  other vias: 76.2,69.85
N$194  (via drill 1.1)
  other vias: 82.55,86.36
N$195  (via drill 1.1)
  other vias: 10.16,78.74
N$196  (via drill 1.2)
  other vias: 48.26,121.92
N$197  (via drill 1.1)
  other vias: 16.51,20.32
N$198  (via drill 1.1)
  other vias: 16.51,36.83
N$199  (via drill 1.1)
  other vias: 11.43,76.2
N$200  (via drill 1.1)
  other vias: 5.08,76.2
N$201  (via drill 1.1)
  other vias: 39.37,19.05
N$202  (via drill 1.1)
  other vias: 39.37,41.91
N$203  (via drill 1.1)
  other vias: 77.47,24.13
N$204  (via drill 1.1)
  other vias: 62.23,33.02
N$205  (via drill 1.1)
  other vias: 66.04,35.56
N$206  (via drill 1.1)
  other vias: 10.16,63.5
N$207  (via drill 1.1)
  other vias: 10.16,55.88
N$208  (via drill 1.1)
  other vias: 87.63,55.88
N$209  (via drill 1.1)
  other vias: 87.63,35.56
N$211  (via drill 1.1)
  other vias: 85.09,45.72
N$212  (via drill 1.1)
  other vias: 82.55,50.8
N$213  (via drill 1.1)
  other vias: 52.07,64.77
N$214  (via drill 1.1)
  other vias: 87.63,64.77
PB3  (via drill 1.1)
  Top 0.406: v76.2,154.94 v66.04,154.94 | v83.82,128.27 v69.85,128.27 | v83.82,157.48 v76.2,157.48 | v74.93,101.6 v67.31,101.6 | v82.55,86.36 v69.85,86.36
  Bottom 0.406: IC8.12 66.04,181.61 67.31,180.34 68.58,181.61 73.66,181.61 73.66,187.96 74.93,187.96 76.2,189.23 77.47,187.96 80.01,187.96 82.55,185.42 82.55,181.61 76.2,175.26 v76.2,157.48 v76.2,154.94 | v66.04,154.94 IC7.12 | v69.85,128.27 IC6.12 | v83.82,157.48 v83.82,128.27 83.82,125.73 74.93,116.84 v74.93,101.6 73.66,100.33 73.66,95.25 71.12,92.71 69.85,92.71 v69.85,86.36 69.85,74.93 67.31,72.39 IC4.12 | v67.31,101.6 IC5.12 | 82.55,77.47 82.55,63.5 81.28,60.96 7.62,60.96 7.62,81.28 IC3.12 | 82.55,77.47 v82.55,86.36 | IC1.4 85.09,22.86 86.36,24.13 93.98,24.13 95.25,25.4 95.25,52.07 90.17,58.42 90.17,76.2 87.63,77.47 82.55,77.47
PB4
  Bottom 0.406: R6.1 36.83,27.94 64.77,27.94 66.04,26.67 66.04,12.7 63.5,10.16 63.5,5.08 66.04,2.54 68.58,2.54 71.12,5.08 71.12,13.97 72.39,15.24 80.01,15.24 82.55,17.78 IC1.5
PB5  (via drill 0.6)
  Top 0.406: v5.08,76.2 v11.43,76.2
  Bottom 0.406: 93.98,45.72 93.98,26.67 92.71,25.4 81.28,25.4 80.01,24.13 IC1.6 | JP1.4 92.71,46.99 93.98,45.72 | 93.98,45.72 93.98,52.07 88.9,57.15 88.9,67.31 86.36,67.31 86.36,58.42 85.09,57.15 73.66,57.15 R8.1 72.39,57.15 71.12,58.42 5.08,58.42 v5.08,76.2 | v11.43,76.2 IC3.14
PB6  (via drill 0.6, 1.1)
  Top 0.406: v77.47,24.13 68.58,29.21 v62.23,33.02 | v66.04,35.56 v82.55,50.8
  Bottom 0.406: v77.47,24.13 IC1.7 | 62.23,34.29 v62.23,33.02 | 62.23,34.29 60.96,35.56 60.71,35.56 U$1.7 | JP1.1 85.09,49.53 v82.55,50.8 | v66.04,35.56 64.77,34.29 62.23,34.29
PB7  (via drill 1.1)
  Top 0.406: v85.09,180.34 v71.12,180.34 | v76.2,152.4 v68.58,152.4 | v86.36,125.73 v69.85,125.73 | v74.93,99.06 v67.31,99.06 | v76.2,69.85 v68.58,69.85 | v85.09,73.66 v76.2,73.66 | v85.09,45.72 v85.09,62.23
  Bottom 0.406: IC8.11 67.31,179.07 68.58,180.34 v71.12,180.34 | v85.09,180.34 85.09,177.8 81.28,173.99 81.28,161.29 | v68.58,152.4 IC7.11 | 81.28,161.29 81.28,152.4 v76.2,152.4 | v69.85,125.73 IC6.11 | v67.31,99.06 IC5.11 | v68.58,69.85 IC4.11 | v76.2,69.85 v76.2,73.66 76.2,97.79 v74.93,99.06 76.2,99.06 77.47,100.33 77.47,116.84 v86.36,125.73 86.36,160.02 85.09,161.29 81.28,161.29 | v85.09,73.66 v85.09,62.23 82.55,59.69 6.35,59.69 6.35,83.82 IC3.11 | 82.55,35.56 85.09,33.02 85.09,27.94 83.82,26.67 81.28,26.67 80.01,25.4 76.2,25.4 74.93,24.13 IC1.8 | 82.55,35.56 R10.1 | 82.55,35.56 83.82,36.83 83.82,38.1 87.63,41.91 88.9,41.91 90.17,43.18 90.17,46.99 JP1.3 87.63,46.99 86.36,45.72 v85.09,45.72
RST
  Bottom 0.406: JP1.5 87.63,43.18 86.36,43.18 85.09,41.91 85.09,40.64 81.28,36.83 | 81.28,36.83 77.47,36.83 76.2,35.56 76.2,30.48 77.47,29.21 78.74,29.21 80.01,27.94 80.01,26.67 73.66,26.67 72.39,25.4 IC1.9 | R1.1 80.01,38.1 81.28,36.83
VCC  (via drill 1.1, 1.2)
  Top 0.406: v76.2,191.77 v67.31,191.77 | v34.29,163.83 v34.29,156.21 | v82.55,177.8 v68.58,177.8 | v74.93,149.86 v66.04,149.86 | v78.74,165.1 v69.85,165.1 | v30.48,133.35 v36.83,133.35 | v25.4,96.52 v35.56,86.36 | v35.56,78.74 35.56,81.28 v20.32,96.52 | v29.21,97.79 v36.83,97.79 | v78.74,142.24 v66.04,142.24 | v78.74,123.19 v67.31,123.19 66.04,121.92 v48.26,121.92 | v71.12,82.55 v66.04,82.55 | v35.56,69.85 v35.56,64.77 | v10.16,63.5 v10.16,55.88 | v69.85,67.31 69.85,64.77 v81.28,53.34
  Bottom 0.254: v69.85,67.31 71.12,67.31 72.39,68.58 72.39,78.74 74.93,78.74 74.93,68.58 77.47,68.58 78.74,69.85 78.74,115.57 87.63,124.46 87.63,180.34 83.82,184.15
  Bottom 0.406: v67.31,191.77 IC8.16 | 36.83,177.8 36.83,184.15 39.37,184.15 40.91,185.69 RGB16.VCC | 36.83,177.8 38.1,176.53 38.37,176.53 RGB15.VCC | RGB14.VCC 40.91,172.45 39.37,173.99 36.83,173.99 | 36.83,173.99 36.83,177.8 | RGB13.VCC 40.91,164.83 40.64,165.1 36.83,165.1 | 36.83,165.1 36.83,173.99 | RGB12.VCC 40.91,155.21 40.64,154.94 35.56,154.94 v34.29,156.21 | 36.83,165.1 35.56,165.1 v34.29,163.83 29.21,158.75 29.21,149.86 | IC8.10 67.31,176.53 v68.58,177.8 | v76.2,191.77 77.47,191.77 83.82,185.42 83.82,184.15 83.82,181.61 82.55,180.34 v82.55,177.8 78.74,173.99 v78.74,165.1 78.74,153.67 74.93,153.67 v74.93,149.86 77.47,149.86 78.74,148.59 v78.74,142.24 v78.74,123.19 | v66.04,149.86 IC7.10 | v69.85,165.1 IC7.16 | RGB8.VCC 40.64,125.73 39.37,124.46 29.21,124.46 | RGB10.VCC 39.64,139.7 29.21,139.7 | RGB11.VCC 40.91,149.59 40.64,149.86 29.21,149.86 | RGB9.VCC 40.64,132.08 39.37,130.81 38.1,130.81 36.83,132.08 v36.83,133.35 | 29.21,133.35 v30.48,133.35 | 29.21,133.35 29.21,139.7 | 29.21,139.7 29.21,149.86 | 29.21,124.46 29.21,133.35 | 40.91,119.11 RGB7.VCC | 40.91,119.11 39.37,120.65 38.1,119.38 36.83,119.38 36.83,116.84 35.56,115.57 35.56,114.3 | 35.56,114.3 34.29,114.3 30.48,110.49 27.94,110.49 25.4,113.03 25.4,115.57 29.21,119.38 29.21,124.46 | 35.56,114.3 36.83,113.03 40.64,113.03 40.91,112.76 RGB6.VCC RGB5.VCC 40.64,102.87 38.1,105.41 36.83,105.41 34.29,102.87 35.56,101.6 31.75,96.52 27.94,96.52 | RGB4.VCC 40.91,96.25 39.37,97.79 v36.83,97.79 | RGB3.VCC 40.91,86.63 40.64,86.36 v35.56,86.36 | RGB2.VCC 40.91,77.74 40.64,77.47 38.1,77.47 36.83,78.74 v35.56,78.74 | 27.94,96.52 v25.4,96.52 v20.32,96.52 19.05,96.52 13.97,91.44 12.7,91.44 11.43,90.17 11.43,87.63 12.7,86.36 IC3.10 15.24,86.36 16.51,85.09 16.51,72.39 15.24,71.12 IC3.16 13.97,67.31 16.51,64.77
  Bottom 0.406: 27.94,96.52 v29.21,97.79 | IC6.16 64.77,138.43 66.04,139.7 v66.04,142.24 | v67.31,123.19 IC6.10 62.23,123.19 60.96,121.92 60.96,119.38 62.23,118.11 62.23,114.3 63.5,113.03 IC5.16 67.31,111.76 71.12,107.95 71.12,97.79 69.85,96.52 IC5.10 | v66.04,82.55 IC4.16 | v71.12,82.55 71.12,68.58 v69.85,67.31 IC4.10 | RGB1.VCC 40.91,71.39 39.37,69.85 v35.56,69.85 | v35.56,64.77 16.51,64.77 | C4.2 C5.1 C6.1 IC2.3 17.78,11.43 3.81,11.43 2.54,12.7 2.54,27.94 6.35,31.75 | 6.35,31.75 21.59,31.75 D4.A | R1.2 71.12,38.1 73.66,38.1 | 73.66,38.1 74.93,36.83 73.66,35.56 73.66,33.02 LED1.A 69.85,29.21 IC1.10 69.85,13.97 67.31,11.43 IC1.30 | 16.51,64.77 17.78,63.5 16.51,62.23 11.43,62.23 v10.16,63.5 | v10.16,55.88 7.62,55.88 2.54,50.8 2.54,46.99 6.35,43.18 6.35,31.75 | JP1.2 91.44,50.8 90.17,52.07 86.36,52.07 85.09,53.34 v81.28,53.34 80.01,52.07 80.01,44.45 77.47,41.91 76.2,41.91 74.93,40.64 74.93,39.37 73.66,38.1 | 40.91,119.11 41.64,119.11 45.72,123.19 46.99,123.19 v48.26,121.92
VCC9V  (via drill 1.1)
  Top 0.406: v16.51,36.83 v16.51,20.32
  Bottom 0.406: C7.+ 8.89,46.99 G1.+ 15.24,39.37 16.51,38.1 v16.51,36.83 | v16.51,20.32 16.51,17.78 IC2.1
